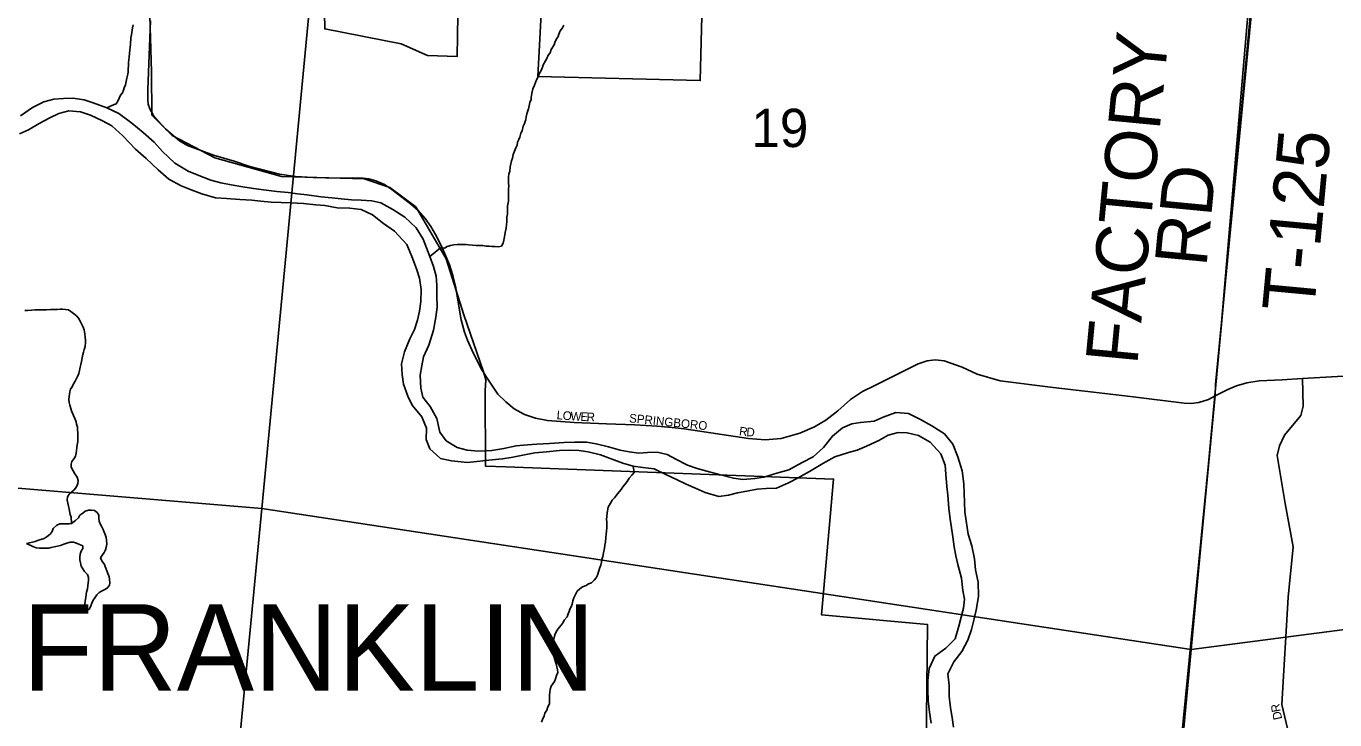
# Model space of a CAD drawing. Extents: x 0 to 1064, y 0 to 440.
# Drawn here: x 184.46 to 207.35, y 357.59 to 369.72 of the extents above; entities that cross this region are included whole.
import ezdxf

# ---------------------------------------------------------------- set-up
doc = ezdxf.new("R2010")
doc.units = 0
for name, color, linetype in [('GM_X_City_Street', 7, 'Continuous'), ('GM_X_City_Street_Text', 7, 'Continuous'), ('GM_X_Corporation', 7, 'Continuous'), ('GM_X_Corporation_Text', 7, 'Continuous'), ('GM_X_County_Road', 7, 'Continuous'), ('GM_X_Minor_River', 7, 'Continuous'), ('GM_X_Section', 7, 'Continuous'), ('GM_X_Section_Text', 7, 'Continuous'), ('GM_X_Township', 7, 'Continuous'), ('GM_X_Township_Road', 7, 'Continuous'), ('GM_X_Township_Road_Text', 7, 'Continuous'), ('GM_X_Township_Subdivision', 7, 'Continuous'), ('GM_X_Township_Subdivision_Text', 7, 'Continuous')]:
    doc.layers.add(name, color=color, linetype=linetype)

msp = doc.modelspace()

# ---------------------------------------------------------------- linework, layer by layer
at = {"layer": 'GM_X_City_Street'}
for points in [[(186.631, 369.809), (186.586, 368.61), (186.589, 368.433), (186.593, 368.356), (186.621, 368.274), (186.685, 368.158), (186.772, 368.054), (186.897, 367.923), (187.03, 367.805), (187.141, 367.714), (187.283, 367.628), (187.735, 367.463), (188.098, 367.356), (188.372, 367.265), (188.891, 367.129), (189.17, 367.089), (189.48, 367.074), (189.696, 367.064), (189.95, 367.062), (190.163, 367.068), (190.352, 367.062), (190.454, 367.05), (190.572, 367.015), (190.726, 366.946), (190.852, 366.859), (191.178, 366.611), (191.312, 366.494), (191.439, 366.356), (191.537, 366.214), (191.617, 366.073), (191.717, 365.882), (191.781, 365.734), (191.864, 365.542), (191.921, 365.359), (191.965, 365.17), (192.065, 364.584), (192.127, 364.369), (192.18, 364.225), (192.275, 364.003), (192.424, 363.72), (192.501, 363.594), (192.567, 363.494)], [(199.3, 363.436), (200.06, 363.81), (200.216, 363.867), (200.356, 363.882), (200.516, 363.864), (200.829, 363.753), (201.091, 363.631), (201.493, 363.517), (202.42, 363.397), (203.129, 363.314), (203.819, 363.234), (204.714, 363.123), (204.833, 363.12), (204.967, 363.138), (205.137, 363.19), (205.255, 363.253)], [(192.567, 363.494), (192.59, 363.458), (192.71, 363.282), (192.846, 363.149), (192.995, 363.026), (193.172, 362.929), (193.366, 362.864), (193.577, 362.82), (194.044, 362.788), (194.606, 362.761), (195.107, 362.744), (195.492, 362.724), (195.757, 362.7), (195.969, 362.676), (197.092, 362.506), (197.386, 362.486), (197.665, 362.508), (197.989, 362.6), (198.247, 362.709), (198.445, 362.825), (198.653, 362.992), (198.877, 363.186), (199.088, 363.331), (199.3, 363.436)]]:
    msp.add_lwpolyline(points, dxfattribs=at)
at = {"layer": 'GM_X_Corporation'}
for points in [[(193.554, 371.592), (193.41, 368.838), (196.248, 368.767), (196.408, 375.08)], [(189.667, 370.487), (189.681, 369.671), (191.015, 369.411), (191.48, 369.204), (191.996, 369.186), (192.04, 371.725)], [(205.847, 370.19), (205.364, 364.533), (205.262, 363.458), (205.255, 363.253), (205.238, 363.077), (204.231, 352.82)], [(186.614, 370.096), (186.649, 368.918), (186.657, 368.162), (187.014, 367.804), (187.757, 367.414), (188.925, 367.088), (190.369, 367.049), (190.822, 366.897), (191.271, 366.559), (191.803, 365.648), (192.113, 364.668), (192.456, 363.672), (192.497, 363.53), (192.486, 363.341), (192.493, 362.021), (192.849, 362.013), (198.58, 361.798), (198.368, 359.424), (200.225, 359.253), (200.178, 354.895)], [(200.178, 354.895), (200.225, 359.253), (198.368, 359.424), (198.58, 361.798), (192.849, 362.013), (192.493, 362.021), (192.486, 363.341), (192.497, 363.53), (192.456, 363.672), (192.113, 364.668), (191.803, 365.648), (191.271, 366.559), (190.822, 366.897), (190.369, 367.049), (188.925, 367.088), (187.757, 367.414), (187.014, 367.804), (186.657, 368.162), (186.649, 368.918), (186.614, 370.096)]]:
    msp.add_lwpolyline(points, dxfattribs=at)
at = {"layer": 'GM_X_County_Road'}
msp.add_lwpolyline([(205.255, 363.253), (205.479, 363.365), (205.628, 363.427), (205.807, 363.483), (206.022, 363.514), (206.424, 363.535), (206.785, 363.555), (207.493, 363.594)], dxfattribs=at)
at = {"layer": 'GM_X_Minor_River'}
for points in [[(185.871, 368.292), (185.998, 368.345), (186.035, 368.361), (186.061, 368.409), (186.086, 368.457), (186.111, 368.512), (186.143, 368.553), (186.162, 368.596), (186.175, 368.638), (186.194, 368.692), (186.208, 368.753), (186.221, 368.807), (186.235, 368.88), (186.242, 368.922), (186.243, 368.977), (186.25, 369.019), (186.251, 369.08), (186.259, 369.177), (186.267, 369.238), (186.274, 369.305), (186.275, 369.353), (186.282, 369.402), (186.291, 369.511), (186.298, 369.566), (186.319, 369.687), (186.332, 369.741)], [(191.518, 365.688), (191.703, 365.841), (191.775, 365.837), (191.819, 365.863), (191.88, 365.88), (191.941, 365.891), (192.002, 365.902), (192.057, 365.901), (192.099, 365.9), (192.154, 365.899), (192.196, 365.892), (192.263, 365.89), (192.329, 365.883), (192.384, 365.881), (192.445, 365.88), (192.505, 365.873), (192.554, 365.872), (192.602, 365.865), (192.663, 365.863), (192.717, 365.856), (192.772, 365.873), (192.803, 365.921), (192.811, 365.976), (192.824, 366.036), (192.838, 366.109), (192.852, 366.187), (192.859, 366.242), (192.866, 366.303), (192.868, 366.376), (192.875, 366.43), (192.877, 366.509), (192.878, 366.57), (192.892, 366.655), (192.894, 366.716), (192.895, 366.776), (192.896, 366.825), (192.897, 366.874), (192.898, 366.922), (192.893, 366.971), (192.894, 367.02), (192.895, 367.081), (192.903, 367.129), (192.916, 367.183), (192.923, 367.256), (192.95, 367.365), (192.963, 367.407), (192.977, 367.474), (193.002, 367.534), (193.022, 367.589), (193.047, 367.637), (193.054, 367.691), (193.073, 367.733), (193.093, 367.776), (193.112, 367.848), (193.131, 367.89), (193.151, 367.969), (193.177, 368.017), (193.196, 368.084), (193.203, 368.132), (193.217, 368.187), (193.243, 368.271), (193.256, 368.326), (193.27, 368.38), (193.289, 368.434), (193.29, 368.477), (193.31, 368.568), (193.323, 368.622), (193.349, 368.688), (193.387, 368.779), (193.407, 368.821), (193.432, 368.887), (193.464, 368.941), (193.489, 369.002), (193.502, 369.044), (193.54, 369.11), (193.572, 369.164), (193.591, 369.212), (193.622, 369.254), (193.642, 369.309), (193.692, 369.393), (193.705, 369.435), (193.73, 369.483), (193.762, 369.537), (193.775, 369.579), (193.8, 369.634), (193.838, 369.688), (193.863, 369.736)], [(191.502, 364.138), (191.582, 364.404), (191.624, 364.628), (191.647, 364.803), (191.64, 365.01), (191.639, 365.186), (191.631, 365.344), (191.58, 365.516), (191.518, 365.688), (191.462, 365.841), (191.405, 365.994), (191.277, 366.192), (191.081, 366.379), (190.872, 366.512), (190.663, 366.627), (190.506, 366.661), (190.318, 366.672), (190.149, 366.683), (189.967, 366.699), (189.804, 366.716), (189.616, 366.732), (189.368, 366.769), (189.205, 366.785), (189.042, 366.808), (188.842, 366.825), (188.654, 366.848), (188.437, 366.878), (188.249, 366.907), (188.044, 366.942), (187.863, 366.977), (187.688, 367.024), (187.448, 367.115), (187.292, 367.18), (187.059, 367.32), (186.84, 367.526), (186.698, 367.687), (186.502, 367.857), (186.306, 368.019), (186.08, 368.189), (185.871, 368.292), (185.63, 368.377), (185.474, 368.43), (185.274, 368.459), (185.11, 368.451), (184.94, 368.443), (184.769, 368.393), (184.572, 368.294), (184.362, 368.148)], [(184.342, 367.832), (184.502, 367.907), (184.686, 368.018), (184.871, 368.117), (185.031, 368.192), (185.202, 368.236), (185.408, 368.218), (185.582, 368.159), (185.792, 368.063), (185.959, 367.974), (186.149, 367.799), (186.368, 367.568), (186.557, 367.405), (186.765, 367.206), (186.954, 367.043), (187.17, 366.928), (187.344, 366.857), (187.53, 366.785), (187.771, 366.718), (187.965, 366.701), (188.195, 366.689), (188.407, 366.672), (188.564, 366.656), (188.746, 366.639), (188.916, 366.635), (189.086, 366.63), (189.31, 366.619), (189.527, 366.595), (189.685, 366.579), (189.896, 366.543), (190.121, 366.537), (190.32, 366.514), (190.518, 366.418), (190.708, 366.267), (190.899, 366.135), (191.117, 365.898), (191.203, 365.69), (191.288, 365.475), (191.338, 365.309), (191.37, 365.114), (191.364, 364.901), (191.336, 364.732), (191.301, 364.575), (191.248, 364.412), (191.171, 364.25), (191.074, 364.022), (191.026, 363.81), (191.034, 363.628), (191.06, 363.457), (191.133, 363.248), (191.208, 363.088), (191.378, 362.884), (191.458, 362.687), (191.453, 362.487), (191.516, 362.327), (191.705, 362.158), (191.898, 362.117), (192.177, 362.086), (192.341, 362.106), (192.548, 362.125), (192.785, 362.149), (192.943, 362.176), (193.145, 362.213), (193.358, 362.256), (193.559, 362.276), (193.784, 362.294), (193.942, 362.302), (194.124, 362.298), (194.287, 362.275), (194.504, 362.221), (194.69, 362.15), (194.895, 362.078), (195.075, 362.025), (195.245, 362.002), (195.444, 361.979), (195.66, 361.87), (195.833, 361.787), (196.001, 361.71), (196.175, 361.632), (196.337, 361.561), (196.572, 361.495), (196.743, 361.515), (196.901, 361.559), (197.066, 361.586), (197.243, 361.618), (197.401, 361.632), (197.583, 361.639), (197.792, 361.731), (197.964, 361.818), (198.161, 361.929), (198.395, 362.068), (198.604, 362.185)], [(184.433, 364.747), (184.482, 364.746), (184.549, 364.751), (184.616, 364.755), (184.682, 364.754), (184.749, 364.758), (184.816, 364.757), (184.883, 364.762), (184.944, 364.76), (184.998, 364.765), (185.053, 364.77), (185.095, 364.769), (185.144, 364.762), (185.198, 364.755), (185.24, 364.729), (185.288, 364.692), (185.336, 364.654), (185.371, 364.611), (185.4, 364.556), (185.424, 364.513), (185.453, 364.451), (185.47, 364.408), (185.487, 364.335), (185.491, 364.28), (185.496, 364.225), (185.495, 364.183), (185.488, 364.116), (185.475, 364.061), (185.461, 364.019), (185.448, 363.977), (185.435, 363.916), (185.428, 363.856), (185.414, 363.801), (185.401, 363.753), (185.394, 363.698), (185.38, 363.644), (185.361, 363.602), (185.336, 363.554), (185.317, 363.512), (185.286, 363.464), (185.26, 363.409), (185.235, 363.367), (185.222, 363.325), (185.215, 363.283), (185.208, 363.24), (185.207, 363.186), (185.212, 363.137), (185.223, 363.088), (185.24, 363.033), (185.251, 362.99), (185.286, 362.91), (185.309, 362.855), (185.332, 362.8), (185.337, 362.757), (185.354, 362.702), (185.359, 362.659), (185.364, 362.604), (185.363, 362.55), (185.362, 362.495), (185.361, 362.453), (185.353, 362.398), (185.346, 362.343), (185.339, 362.295), (185.332, 362.253)], [(200.678, 357.46), (200.652, 357.625), (200.626, 357.796), (200.601, 358.003), (200.605, 358.185), (200.581, 358.392), (200.683, 358.602), (200.821, 358.781), (200.93, 358.979), (200.995, 359.165), (201.042, 359.353), (201.078, 359.534), (201.114, 359.752), (201.108, 359.995), (201.065, 360.209), (201.046, 360.404), (200.997, 360.63), (200.935, 360.832), (200.899, 361.064), (200.879, 361.222), (200.871, 361.386), (200.863, 361.551), (200.861, 361.715), (200.831, 361.94), (200.752, 362.185), (200.667, 362.406), (200.52, 362.586), (200.299, 362.731), (200.102, 362.84), (199.892, 362.942), (199.668, 362.96), (199.448, 362.88), (199.288, 362.812), (199.051, 362.787), (198.899, 362.761), (198.739, 362.692), (198.559, 362.55), (198.402, 362.348), (198.222, 362.188), (198.032, 362.084), (197.798, 361.956), (197.59, 361.9), (197.358, 361.833), (197.205, 361.807), (196.992, 361.788), (196.829, 361.81), (196.582, 361.877), (196.425, 361.918), (196.197, 361.984), (196.028, 362.043), (195.831, 362.139), (195.669, 362.228), (195.494, 362.269), (195.324, 362.261), (195.172, 362.253), (195.003, 362.276), (194.846, 362.304), (194.641, 362.358), (194.43, 362.412), (194.261, 362.44), (194.055, 362.445), (193.866, 362.438), (193.611, 362.42), (193.392, 362.407), (193.228, 362.393), (193.028, 362.38), (192.814, 362.331), (192.601, 362.294), (192.376, 362.287), (192.17, 362.305), (191.995, 362.352), (191.804, 362.466), (191.693, 362.62), (191.639, 362.859), (191.523, 363.068), (191.399, 363.229), (191.361, 363.388), (191.349, 363.614), (191.377, 363.777), (191.406, 363.934), (191.502, 364.138)], [(198.604, 362.185), (198.843, 362.264), (198.996, 362.302), (199.155, 362.371), (199.37, 362.469), (199.537, 362.562), (199.708, 362.613), (199.865, 362.603), (200.064, 362.561), (200.268, 362.441), (200.456, 362.241), (200.53, 362.039), (200.544, 361.881), (200.563, 361.667), (200.577, 361.515), (200.595, 361.29), (200.621, 361.095), (200.641, 360.942), (200.667, 360.784), (200.687, 360.613), (200.719, 360.454), (200.752, 360.302), (200.818, 360.063), (200.843, 359.85), (200.869, 359.697), (200.853, 359.54), (200.813, 359.383), (200.772, 359.226), (200.706, 359.003), (200.544, 358.837), (200.352, 358.702), (200.255, 358.485), (200.232, 358.273), (200.227, 358.109), (200.235, 357.921), (200.26, 357.72), (200.285, 357.531)], [(185.332, 362.253), (185.319, 362.198), (185.3, 362.156), (185.256, 362.102), (185.243, 362.06), (185.248, 362.005), (185.283, 361.943), (185.312, 361.888), (185.353, 361.832), (185.37, 361.771), (185.363, 361.717), (185.337, 361.663), (185.3, 361.609), (185.257, 361.573), (185.213, 361.532), (185.182, 361.484), (185.175, 361.429), (185.185, 361.374), (185.197, 361.325), (185.208, 361.276), (185.219, 361.233), (185.23, 361.178), (185.247, 361.129), (185.251, 361.02)], [(195.075, 362.025), (195.095, 361.912), (195.052, 361.865), (195.008, 361.811), (194.97, 361.757), (194.927, 361.703), (194.896, 361.661), (194.864, 361.613), (194.833, 361.572), (194.783, 361.518), (194.746, 361.47), (194.708, 361.428), (194.677, 361.374), (194.639, 361.308), (194.625, 361.242), (194.618, 361.199), (194.617, 361.145), (194.61, 361.09), (194.615, 361.047), (194.614, 360.993), (194.613, 360.944), (194.606, 360.889), (194.604, 360.829), (194.597, 360.78), (194.589, 360.695), (194.582, 360.641), (194.575, 360.586), (194.555, 360.507), (194.547, 360.441), (194.528, 360.393), (194.521, 360.344), (194.508, 360.29), (194.488, 360.235), (194.475, 360.193), (194.449, 360.115), (194.43, 360.072), (194.393, 360.031), (194.349, 359.983), (194.294, 359.966), (194.251, 359.936), (194.19, 359.913), (194.141, 359.878), (194.097, 359.836), (194.059, 359.764), (194.04, 359.722), (194.021, 359.668), (194.007, 359.607), (193.988, 359.565), (193.969, 359.523), (193.956, 359.481), (193.937, 359.439), (193.918, 359.39), (193.868, 359.331), (193.849, 359.289), (193.817, 359.241), (193.78, 359.199), (193.743, 359.157), (193.711, 359.091), (193.698, 359.049), (193.685, 359), (193.677, 358.952), (193.676, 358.891), (193.675, 358.836), (193.68, 358.769), (193.69, 358.702), (193.701, 358.659), (193.713, 358.617), (193.73, 358.568), (193.741, 358.513), (193.752, 358.458), (193.757, 358.415), (193.737, 358.361), (193.718, 358.306), (193.699, 358.258), (193.668, 358.216), (193.642, 358.174), (193.623, 358.114), (193.616, 358.072), (193.609, 358.017), (193.613, 357.956), (193.612, 357.914), (193.611, 357.865), (193.58, 357.811), (193.567, 357.757), (193.529, 357.703), (193.516, 357.654), (193.49, 357.594), (193.471, 357.546)], [(184.466, 360.672), (184.515, 360.683), (184.57, 360.694), (184.613, 360.706), (184.674, 360.728), (184.717, 360.74), (184.772, 360.757), (184.827, 360.792), (184.876, 360.834), (184.914, 360.881), (184.933, 360.93), (184.995, 360.989), (185.05, 361.012), (185.099, 361.017), (185.153, 361.016), (185.208, 361.015), (185.251, 361.02), (185.319, 361.073), (185.374, 361.121), (185.399, 361.163), (185.449, 361.198), (185.492, 361.234), (185.547, 361.251), (185.602, 361.256), (185.656, 361.248), (185.698, 361.211), (185.727, 361.168), (185.732, 361.113), (185.737, 361.058), (185.754, 361.015), (185.778, 360.972), (185.807, 360.917), (185.824, 360.868), (185.841, 360.825), (185.858, 360.776), (185.863, 360.727), (185.868, 360.66), (185.86, 360.599), (185.847, 360.557), (185.822, 360.515), (185.791, 360.473), (185.759, 360.419), (185.788, 360.358), (185.824, 360.314), (185.9, 360.116)], [(185.9, 360.116), (185.91, 360.094), (185.915, 360.039), (185.92, 359.984), (185.913, 359.941), (185.882, 359.894), (185.832, 359.864), (185.777, 359.835), (185.734, 359.812), (185.697, 359.77), (185.659, 359.722), (185.628, 359.68), (185.609, 359.626), (185.589, 359.578), (185.558, 359.518), (185.515, 359.512), (185.492, 359.562), (185.487, 359.61), (185.488, 359.659), (185.502, 359.725), (185.509, 359.78), (185.516, 359.822), (185.529, 359.877), (185.536, 359.931), (185.544, 359.98), (185.551, 360.022), (185.546, 360.077), (185.529, 360.126), (185.481, 360.182), (185.452, 360.225), (185.423, 360.274), (185.406, 360.33), (185.395, 360.384), (185.396, 360.433), (185.403, 360.482), (185.422, 360.536), (185.447, 360.584), (185.448, 360.627), (185.394, 360.652), (185.34, 360.677), (185.286, 360.691), (185.225, 360.692), (185.17, 360.675), (185.115, 360.658), (185.06, 360.635), (185.005, 360.624), (184.95, 360.613), (184.896, 360.602), (184.853, 360.591), (184.798, 360.586), (184.744, 360.587), (184.689, 360.588), (184.635, 360.596), (184.574, 360.615), (184.466, 360.672)]]:
    msp.add_lwpolyline(points, dxfattribs=at)
at = {"layer": 'GM_X_Section'}
for points in [[(190.108, 377.348), (188.579, 361.283), (171.779, 362.681), (173.24, 378.953)], [(223.805, 378.004), (222.155, 361.074), (204.837, 358.818), (206.359, 375.143)], [(206.359, 375.143), (204.837, 358.818), (188.579, 361.283), (190.108, 377.348)], [(188.579, 361.283), (187.008, 344.881), (170.322, 346.561), (171.779, 362.681)], [(204.837, 358.818), (203.317, 342.596), (187.008, 344.881), (188.579, 361.283)], [(222.155, 361.074), (220.661, 344.384), (203.317, 342.596), (204.837, 358.818)]]:
    msp.add_lwpolyline(points, close=True, dxfattribs=at)
at = {"layer": 'GM_X_Township'}
for points in [[(202.693, 335.755), (203.722, 347.141), (205.238, 363.077), (205.255, 363.253), (205.262, 363.458), (205.364, 364.533), (206.065, 371.769)], [(206.065, 371.769), (205.364, 364.533), (205.262, 363.458), (205.255, 363.253), (205.238, 363.077), (203.722, 347.141), (202.693, 335.755)]]:
    msp.add_lwpolyline(points, dxfattribs=at)
at = {"layer": 'GM_X_Township_Road'}
msp.add_lwpolyline([(205.255, 363.253), (205.262, 363.458), (205.364, 364.533), (206.065, 371.769)], dxfattribs=at)
at = {"layer": 'GM_X_Township_Subdivision'}
msp.add_lwpolyline([(206.434, 355.68), (206.543, 357.338), (206.423, 357.854), (206.532, 359.733), (206.62, 360.611), (206.478, 361.369), (206.337, 362.209), (206.378, 362.376), (206.466, 362.566), (206.752, 362.907), (206.796, 363.071), (206.785, 363.555)], dxfattribs=at)

# ---------------------------------------------------------------- texts
at = {"layer": 'GM_X_City_Street_Text'}
for s, height, rotation, p in [('L', 0.152, 355.2954, (193.732, 362.845)), ('O', 0.152, 355.2745, (193.838, 362.836)), ('W', 0.152, 356.6196, (193.975, 362.825)), ('E', 0.152, 357.7563, (194.151, 362.814)), ('R', 0.152, 357.7725, (194.258, 362.81)), ('SPRINGBORO', 0.1515, 354.1753, (194.998, 362.791)), ('R', 0.152, 352.155, (196.921, 362.564)), ('D', 0.152, 356.4526, (197.052, 362.547))]:
    msp.add_text(s, height=height, rotation=rotation, dxfattribs=at).set_placement(p)
at = {"layer": 'GM_X_Corporation_Text'}
msp.add_text('FRANKLIN', height=1.5152, rotation=0, dxfattribs=at).set_placement((184.392, 358.094))
at = {"layer": 'GM_X_Section_Text'}
msp.add_text('19', height=0.6697, rotation=0, dxfattribs=at).set_placement((197.143, 367.604))
at = {"layer": 'GM_X_Township_Road_Text'}
for s, rotation, p in [('FACTORY', 84.5523, (203.891, 363.781)), ('T-125', 84.6536, (206.981, 364.696)), ('RD', 84.5353, (205.101, 365.496))]:
    msp.add_text(s, height=0.9091, rotation=rotation, dxfattribs=at).set_placement(p)
at = {"layer": 'GM_X_Township_Subdivision_Text'}
for s, rotation, p in [('R', 99.7337, (206.4, 357.733)), ('D', 102.778, (206.429, 357.605))]:
    msp.add_text(s, height=0.152, rotation=rotation, dxfattribs=at).set_placement(p)

doc.saveas('drawing.dxf')
